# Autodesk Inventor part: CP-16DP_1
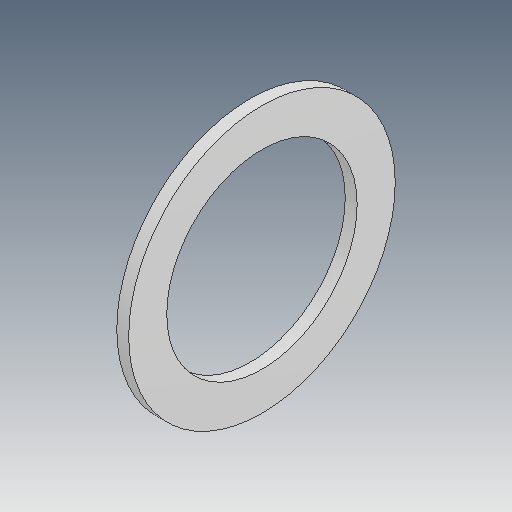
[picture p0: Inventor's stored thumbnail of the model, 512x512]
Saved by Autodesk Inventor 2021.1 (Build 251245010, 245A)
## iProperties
Created: 2021-06
Part Number: CP-16DP_1
Material: Ogólny
Document SubType Name: Modeling
Designer: user
Density: 1 g/cm^3
Appearance: Domyślna
Author: user
Revision Number: ÈÎºÎ
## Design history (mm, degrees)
feature "ÊäÈë1"
node "Bryła1"
